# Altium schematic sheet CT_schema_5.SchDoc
size 218 x 258 mm
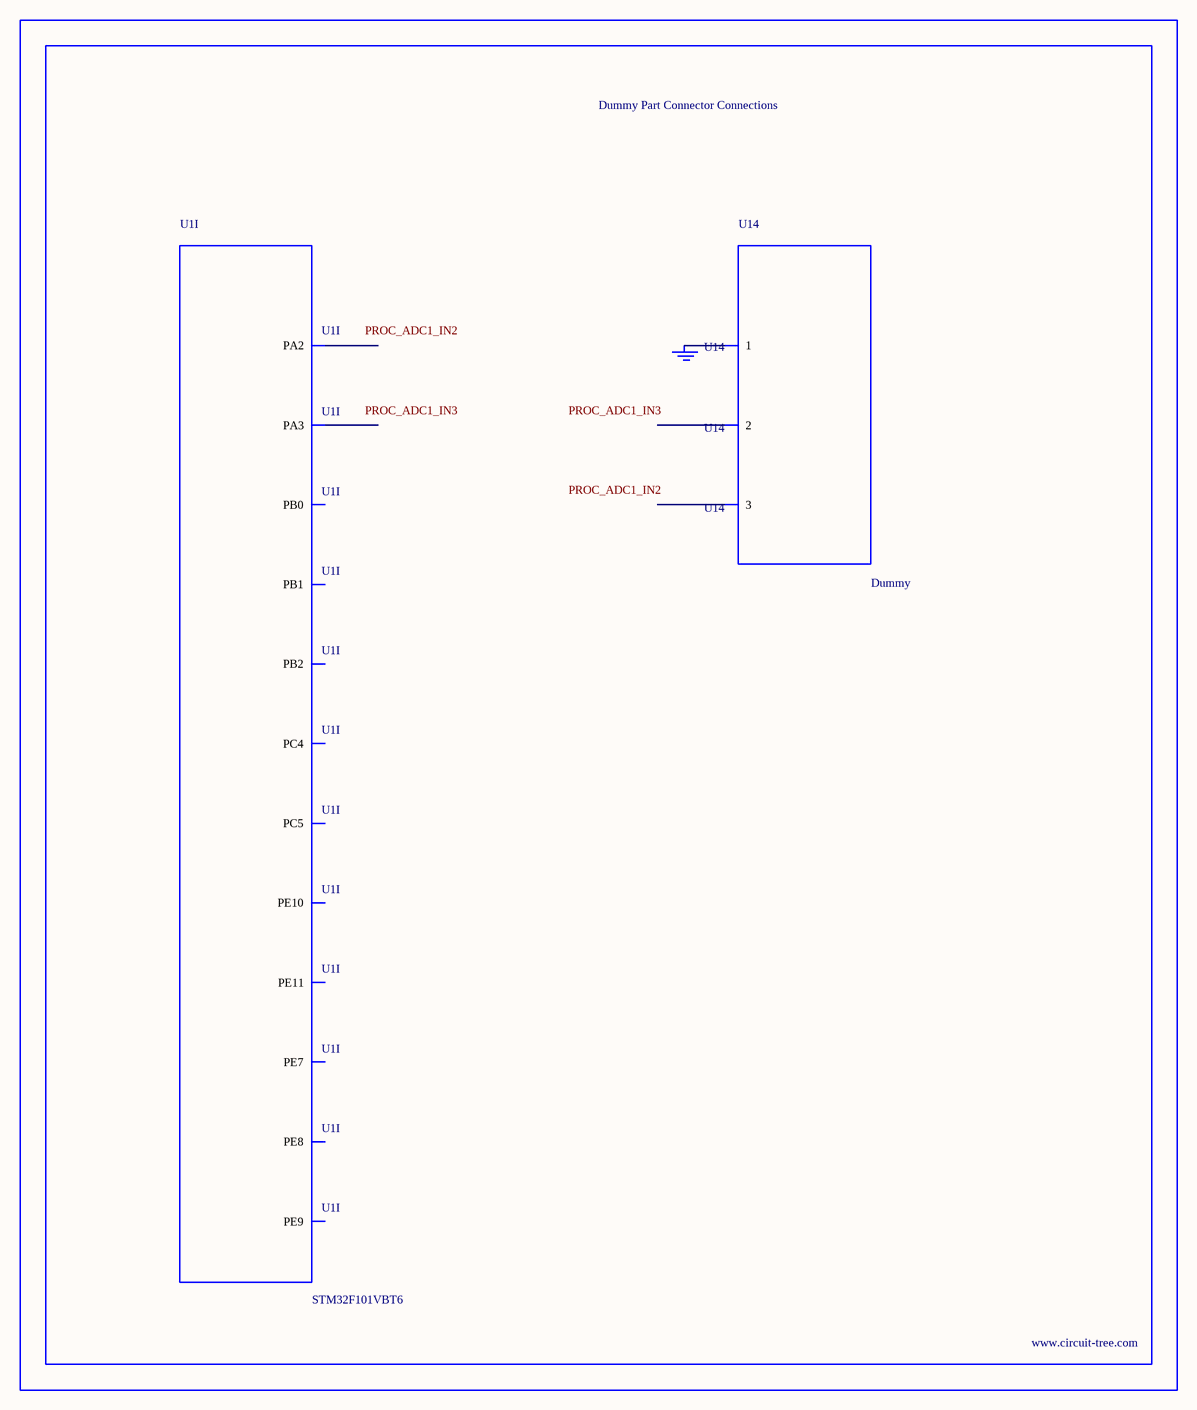
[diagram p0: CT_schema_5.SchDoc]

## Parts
BORDER4  (no value)
GND_INSTANCE_4_0  (no value)
U1  STM32F101VBT6  [LQFP100]  (part I of 9)
U14  Dummy  [DUMMY_PACKAGE_136]

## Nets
NetGND_INSTANCE_4_0_0: GND_INSTANCE_4_0.0(GND) U14.1

Not connected (* = marked no-connect by the designer): U1 25(PA2) 26(PA3) 33(PC4) 34(PC5) 35(PB0) 36(PB1) 37(PB2) 38(PE7) 39(PE8) 40(PE9) 41(PE10) 42(PE11); U14 2 3

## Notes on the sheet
- Labels drawn without touching a wire or pin: PROC_ADC1_IN2, PROC_ADC1_IN3

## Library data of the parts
BORDER4 = BORDER_PAGE4
GND_INSTANCE_4_0 = GND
